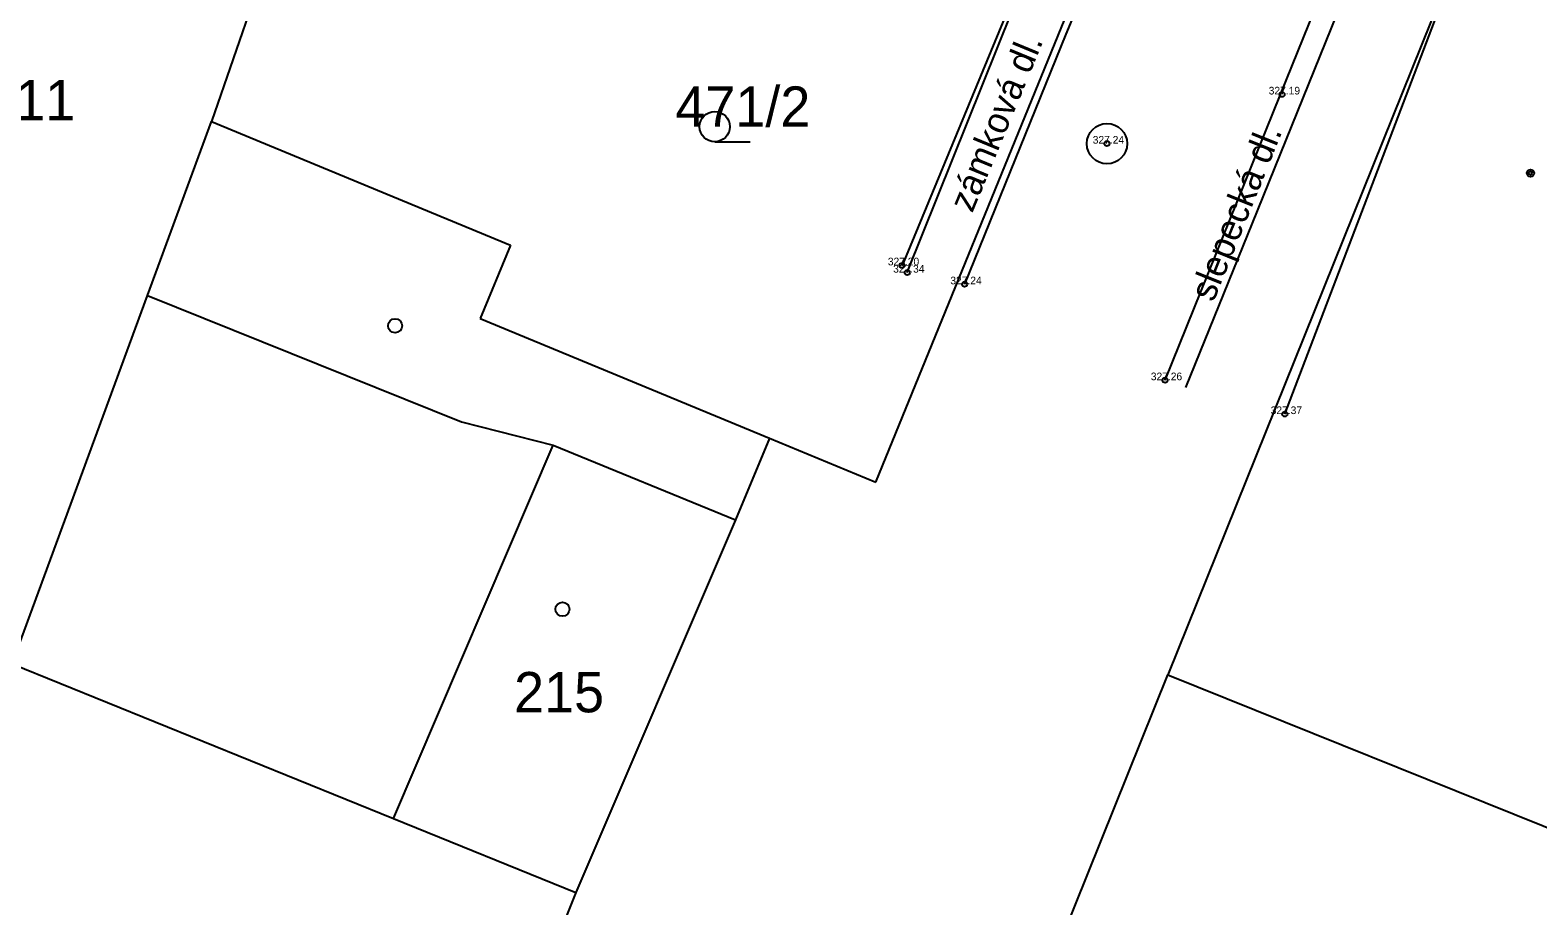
# Model space of a CAD drawing. Extents: x -643859 to -643594, y -1190913 to -1190609.
# Drawn here: x -643721.86 to -643684.48, y -1190816.35 to -1190794.62 of the extents above; entities that cross this region are included whole.
import ezdxf

# ---------------------------------------------------------------- set-up
doc = ezdxf.new("R2010")
doc.units = 0
for name, color, linetype in [('Bodové objekty kanalizace', 7, 'Continuous'), ('Bodové objekty katastrální', 7, 'Continuous'), ('Bodové objekty značky budov', 7, 'Continuous'), ('Budovy', 7, 'Continuous'), ('Default', 7, 'Continuous'), ('Hranice parcel', 7, 'Continuous'), ('Ploty_podezdívky', 7, 'Continuous'), ('Popis povrchů', 7, 'Continuous'), ('Rozhraní', 7, 'Continuous'), ('Rozhraní_ schody_ zdi', 7, 'Continuous'), ('Svodidla_zábradlí', 7, 'Continuous'), ('Vrstva 1', 7, 'Continuous'), ('Vrstva 11', 7, 'Continuous'), ('Vrstva 38', 7, 'Continuous'), ('Vrstva 63', 7, 'Continuous')]:
    doc.layers.add(name, color=color, linetype=linetype)

msp = doc.modelspace()

# ---------------------------------------------------------------- linework, layer by layer
at = {"layer": 'Bodové objekty kanalizace'}
msp.add_circle((-643695.16, -1190797.44), 0.5, dxfattribs=at)
at = {"layer": 'Bodové objekty katastrální'}
msp.add_line((-643704.884, -1190797.394), (-643704.009, -1190797.394), dxfattribs=at)
msp.add_circle((-643704.884, -1190797.019), 0.375, dxfattribs=at)
at = {"layer": 'Bodové objekty značky budov'}
for radius in [0.09, 0.0398]:
    msp.add_circle((-643684.661, -1190798.17), radius, dxfattribs=at)
at = {"layer": 'Budovy'}
msp.add_lwpolyline([(-643690.75, -1190804.15), (-643686.4, -1190792.73), (-643686.288, -1190792.773), (-643684.13, -1190786.91), (-643684.1, -1190786.92), (-643679.438, -1190788.637)], dxfattribs=at)
at = {"layer": 'Default'}
for centre in [(-643690.82, -1190796.22), (-643695.16, -1190797.44), (-643700.24, -1190800.46), (-643700.11, -1190800.64), (-643698.69, -1190800.93), (-643693.72, -1190803.31), (-643690.75, -1190804.15)]:
    msp.add_circle(centre, 0.0625, dxfattribs=at)
at = {"layer": 'Hranice parcel'}
for p, q in [((-643713.38, -1190785.38), (-643717.36, -1190796.89)), ((-643684.1, -1190786.89), (-643693.65, -1190810.62)), ((-643700.89, -1190805.84), (-643696.04, -1190793.95)), ((-643718.95, -1190801.21), (-643717.36, -1190796.89)), ((-643717.36, -1190796.89), (-643709.95, -1190799.96)), ((-643709.95, -1190799.96), (-643710.7, -1190801.78)), ((-643722.3, -1190810.35), (-643718.95, -1190801.21)), ((-643710.7, -1190801.78), (-643703.53, -1190804.75)), ((-643703.53, -1190804.75), (-643704.37, -1190806.77)), ((-643703.53, -1190804.75), (-643700.89, -1190805.84)), ((-643704.37, -1190806.77), (-643708.33, -1190816.02)), ((-643722.3, -1190810.35), (-643712.85, -1190814.18)), ((-643698.1, -1190821.69), (-643693.65, -1190810.62)), ((-643693.65, -1190810.62), (-643638.73, -1190832.74)), ((-643712.85, -1190814.18), (-643708.33, -1190816.02)), ((-643708.33, -1190816.02), (-643712.35, -1190826.06))]:
    msp.add_line(p, q, dxfattribs=at)
at = {"layer": 'Ploty_podezdívky'}
msp.add_lwpolyline([(-643699.63, -1190792.26), (-643698.07, -1190793.04), (-643697.64, -1190794.19), (-643700.24, -1190800.46)], dxfattribs=at)
at = {"layer": 'Rozhraní'}
for points in [[(-643693.72, -1190803.31), (-643690.856, -1190796.218), (-643685.61, -1190783.24), (-643685.45, -1190783.28), (-643685.1, -1190782.42), (-643685.22, -1190782.33), (-643682.77, -1190776.31), (-643680.06, -1190769.62)], [(-643695.2, -1190792.36), (-643696.18, -1190794.72), (-643698.69, -1190800.93)]]:
    msp.add_lwpolyline(points, dxfattribs=at)
at = {"layer": 'Rozhraní_ schody_ zdi'}
for points in [[(-643693.205, -1190803.493), (-643691.553, -1190799.413), (-643682.333, -1190776.603), (-643679.509, -1190769.675)], [(-643700.11, -1190800.64), (-643697.49, -1190794.11), (-643696.25, -1190790.98), (-643696.16, -1190790.583), (-643696.13, -1190790.39), (-643696.1, -1190790.136), (-643696.09, -1190789.97), (-643696.086, -1190789.68), (-643696.1, -1190789.48), (-643696.11, -1190789.28), (-643696.141, -1190789.05), (-643696.16, -1190788.96), (-643696.213, -1190788.663), (-643696.317, -1190788.332), (-643696.43, -1190788.03), (-643696.556, -1190787.776), (-643696.742, -1190787.479), (-643696.94, -1190787.22), (-643696.46, -1190786.23), (-643696.21, -1190785.72)]]:
    msp.add_lwpolyline(points, dxfattribs=at)
at = {"layer": 'Vrstva 1'}
for p, q in [((-643718.95, -1190801.21), (-643711.16, -1190804.34)), ((-643711.16, -1190804.34), (-643708.89, -1190804.92)), ((-643712.85, -1190814.18), (-643708.89, -1190804.92)), ((-643708.89, -1190804.92), (-643704.37, -1190806.77))]:
    msp.add_line(p, q, dxfattribs=at)
at = {"layer": 'Vrstva 11'}
msp.add_circle((-643708.66, -1190808.99), 0.175, dxfattribs=at)
at = {"layer": 'Vrstva 38'}
msp.add_circle((-643712.81, -1190801.96), 0.175, dxfattribs=at)

# ---------------------------------------------------------------- texts
at = {"layer": 'Popis povrchů'}
for s, height, rotation, p in [('zámková dl.', 0.64996, 67.5797, (-643698.5, -1190799.176)), ('slepecká dl.', 0.64999, 68.0617, (-643692.521, -1190801.39))]:
    msp.add_text(s, height=height, rotation=rotation, dxfattribs=at).set_placement(p)
at = {"layer": 'Svodidla_zábradlí'}
for s, p in [('327.19', (-643691.15, -1190796.22)), ('327.24', (-643695.513, -1190797.44)), ('327.20', (-643700.593, -1190800.46)), ('327.34', (-643700.461, -1190800.64)), ('327.24', (-643699.043, -1190800.93)), ('327.26', (-643694.073, -1190803.31)), ('327.37', (-643691.101, -1190804.15))]:
    msp.add_text(s, height=0.19, dxfattribs=at).set_placement(p)
at = {"layer": 'Vrstva 63'}
for s, p in [('469/11', (-643724.829, -1190796.859)), ('471/2', (-643705.86, -1190797.02)), ('215', (-643709.859, -1190811.549))]:
    msp.add_text(s, height=1, dxfattribs=at).set_placement(p)

doc.saveas('drawing.dxf')
